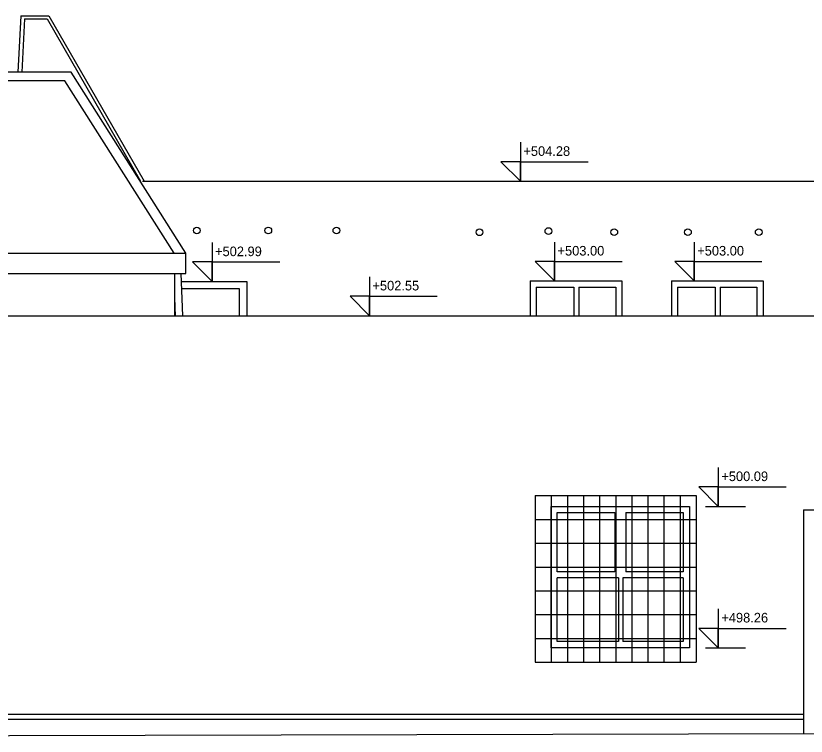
# Model space of a CAD drawing. Extents: x 224 to 311.2, y 493.1 to 511.4.
# Drawn here: x 279.82 to 290.02, y 497.12 to 506.42 of the extents above; entities that cross this region are included whole.
import ezdxf

# ---------------------------------------------------------------- set-up
doc = ezdxf.new("R2010")
doc.units = 0
for name, color, linetype in [('mriz', 7, 'Continuous'), ('okap', 7, 'Continuous'), ('okna', 7, 'Continuous'), ('strecha_sikma', 7, 'Continuous'), ('teren', 7, 'Continuous'), ('zakl_tenka', 7, 'Continuous'), ('zebrik', 7, 'Continuous'), ('znaceni', 7, 'Continuous')]:
    doc.layers.add(name, color=color, linetype=linetype)

msp = doc.modelspace()

# ---------------------------------------------------------------- linework, layer by layer
at = {"layer": 'mriz'}
for p, q in [((286.524, 500.224), (288.601, 500.224)), ((286.524, 500.224), (286.524, 498.074)), ((286.731, 500.224), (286.731, 498.074)), ((286.939, 500.224), (286.939, 498.074)), ((287.147, 500.224), (287.147, 498.074)), ((287.354, 500.224), (287.354, 498.074)), ((287.562, 500.224), (287.562, 498.074)), ((287.77, 500.224), (287.77, 498.074)), ((287.978, 500.224), (287.978, 498.074)), ((288.185, 500.224), (288.185, 498.074)), ((288.393, 500.224), (288.393, 498.074)), ((288.601, 500.224), (288.601, 498.074)), ((286.524, 499.917), (288.601, 499.917)), ((286.524, 499.61), (288.601, 499.61)), ((286.524, 499.303), (288.601, 499.303)), ((286.524, 498.996), (288.601, 498.996)), ((286.524, 498.689), (288.601, 498.689)), ((286.524, 498.382), (288.601, 498.382)), ((286.524, 498.074), (288.601, 498.074))]:
    msp.add_line(p, q, dxfattribs=at)
at = {"layer": 'okap'}
for p, q in [((282.012, 503.091), (282.012, 503.354)), ((265.078, 503.091), (282.012, 503.091)), ((281.946, 503.091), (281.968, 502.546)), ((281.865, 502.775), (281.875, 502.542))]:
    msp.add_line(p, q, dxfattribs=at)
at = {"layer": 'okna'}
for p, q in [((281.95, 502.895), (282.699, 502.895)), ((282.699, 502.895), (282.699, 502.546)), ((286.537, 502.912), (286.537, 502.546)), ((286.537, 502.912), (287.02, 502.912)), ((287.02, 502.912), (287.02, 502.546)), ((287.085, 502.912), (287.085, 502.546)), ((287.085, 502.912), (287.562, 502.912)), ((287.562, 502.912), (287.562, 502.546)), ((288.361, 502.912), (288.361, 502.546)), ((288.361, 502.912), (288.845, 502.912)), ((288.845, 502.912), (288.845, 502.546)), ((288.909, 502.912), (288.909, 502.546)), ((288.909, 502.912), (289.386, 502.912)), ((289.386, 502.912), (289.386, 502.546)), ((287.55, 500.006), (287.55, 499.24)), ((287.692, 500.006), (287.692, 499.24)), ((287.55, 499.24), (286.807, 499.24)), ((287.598, 499.165), (286.807, 499.165)), ((287.598, 499.165), (287.598, 498.342)), ((287.655, 499.165), (287.655, 498.342)), ((288.435, 499.165), (287.655, 499.165)), ((288.435, 499.24), (287.692, 499.24))]:
    msp.add_line(p, q, dxfattribs=at)
for points in [[(286.807, 499.24), (286.807, 500.006), (287.55, 500.006)], [(287.692, 500.006), (288.435, 500.006), (288.435, 499.24)], [(287.598, 498.342), (286.807, 498.342), (286.807, 499.165)], [(288.435, 499.165), (288.435, 498.342)], [(288.435, 498.342), (287.655, 498.342)]]:
    msp.add_lwpolyline(points, dxfattribs=at)
at = {"layer": 'strecha_sikma'}
for p, q in [((280.531, 505.686), (266.513, 505.686)), ((282.012, 503.354), (280.531, 505.686)), ((280.451, 505.576), (266.629, 505.576)), ((281.861, 503.354), (280.451, 505.576)), ((265.078, 503.354), (282.012, 503.354))]:
    msp.add_line(p, q, dxfattribs=at)
at = {"layer": 'teren'}
msp.add_lwpolyline([(260.099, 497.175), (263.904, 497.145), (275.27, 497.123), (276.223, 497.121), (292.012, 497.161), (304.698, 497.168)], dxfattribs=at)
at = {"layer": 'zakl_tenka'}
for p, q in [((281.454, 504.283), (296.565, 504.283)), ((281.865, 503.091), (281.865, 502.546)), ((281.95, 502.989), (282.801, 502.989)), ((282.801, 502.989), (282.801, 502.546)), ((286.458, 502.996), (287.643, 502.996)), ((286.458, 502.996), (286.458, 502.546)), ((287.643, 502.996), (287.643, 502.546)), ((288.282, 502.996), (289.468, 502.996)), ((288.282, 502.996), (288.282, 502.546)), ((289.468, 502.996), (289.468, 502.546)), ((279.583, 502.546), (311.105, 502.546)), ((289.987, 500.043), (291.975, 500.043)), ((289.987, 500.043), (289.987, 497.156)), ((260.099, 497.405), (289.987, 497.405)), ((260.099, 497.339), (289.987, 497.339))]:
    msp.add_line(p, q, dxfattribs=at)
msp.add_lwpolyline([(286.727, 500.086), (288.515, 500.086), (288.515, 498.262), (286.727, 498.262)], close=True, dxfattribs=at)
for centre in [(282.153, 503.645), (283.077, 503.645), (283.956, 503.645), (285.804, 503.622), (286.693, 503.638), (287.544, 503.623), (288.495, 503.623), (289.409, 503.623)]:
    msp.add_circle(centre, 0.0431, dxfattribs=at)
at = {"layer": 'zebrik'}
for p, q in [((279.881, 506.415), (279.843, 505.686)), ((279.881, 506.415), (280.241, 506.415)), ((280.241, 506.415), (281.472, 504.283)), ((279.929, 506.375), (279.893, 505.686)), ((279.929, 506.375), (280.22, 506.375)), ((280.22, 506.375), (281.428, 504.283))]:
    msp.add_line(p, q, dxfattribs=at)
at = {"layer": 'znaceni'}
for p, q in [((286.331, 504.783), (286.331, 504.283)), ((286.331, 504.533), (286.081, 504.533)), ((286.081, 504.533), (286.331, 504.283)), ((286.331, 504.283), (286.331, 504.533)), ((286.331, 504.533), (287.206, 504.533)), ((282.35, 503.489), (282.35, 502.989)), ((286.772, 503.496), (286.772, 502.996)), ((288.576, 503.496), (288.576, 502.996)), ((282.35, 503.239), (282.1, 503.239)), ((282.1, 503.239), (282.35, 502.989)), ((282.35, 502.989), (282.35, 503.239)), ((282.35, 503.239), (283.225, 503.239)), ((286.772, 503.246), (286.522, 503.246)), ((286.522, 503.246), (286.772, 502.996)), ((286.772, 502.996), (286.772, 503.246)), ((286.772, 503.246), (287.647, 503.246)), ((288.576, 503.246), (288.326, 503.246)), ((288.326, 503.246), (288.576, 502.996)), ((288.576, 502.996), (288.576, 503.246)), ((288.576, 503.246), (289.451, 503.246)), ((284.383, 503.046), (284.383, 502.546)), ((284.383, 502.796), (284.133, 502.796)), ((284.133, 502.796), (284.383, 502.546)), ((284.383, 502.546), (284.383, 502.796)), ((284.383, 502.796), (285.257, 502.796)), ((288.887, 500.586), (288.887, 500.086)), ((288.887, 500.336), (288.637, 500.336)), ((288.637, 500.336), (288.887, 500.086)), ((288.887, 500.086), (288.887, 500.336)), ((288.887, 500.336), (289.762, 500.336)), ((288.72, 500.086), (289.236, 500.086)), ((288.887, 498.762), (288.887, 498.262)), ((288.887, 498.512), (288.637, 498.512)), ((288.637, 498.512), (288.887, 498.262)), ((288.887, 498.262), (288.887, 498.512)), ((288.887, 498.512), (289.762, 498.512)), ((288.72, 498.262), (289.236, 498.262))]:
    msp.add_line(p, q, dxfattribs=at)

# ---------------------------------------------------------------- texts
for s, p in [('+504.28', (286.37, 504.608)), ('+502.99', (282.389, 503.314)), ('+503.00', (286.811, 503.322)), ('+503.00', (288.615, 503.322)), ('+502.55', (284.421, 502.872)), ('+500.09', (288.926, 500.412)), ('+498.26', (288.926, 498.588))]:
    msp.add_text(s, height=0.124, dxfattribs=at).set_placement(p)

doc.saveas('drawing.dxf')
